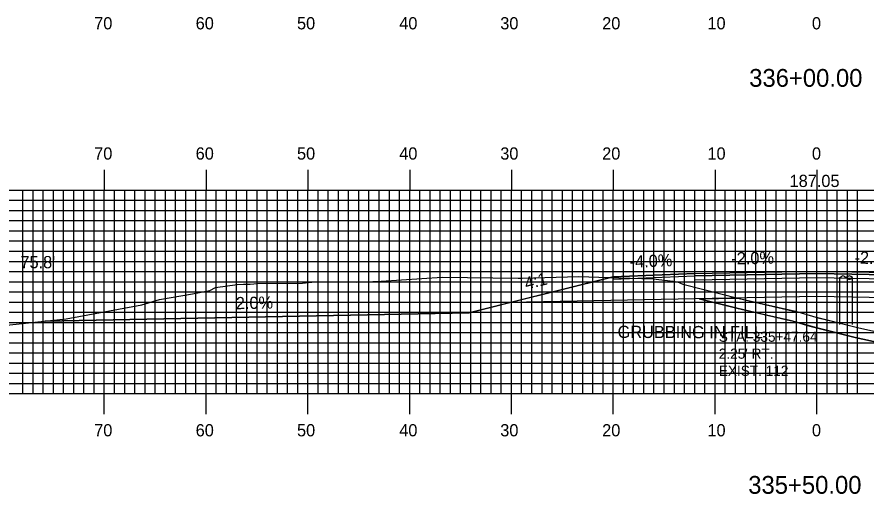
# Model space of a CAD drawing. Extents: x 1823573 to 1823916, y 442591 to 442811.
# Drawn here: x 1823659.7 to 1823743.1, y 442638.8 to 442685.7 of the extents above; entities that cross this region are included whole.
import ezdxf

# ---------------------------------------------------------------- set-up
doc = ezdxf.new("R2010")
doc.units = 0
for name, color, linetype in [('ANNOTATION', 7, 'Continuous'), ('D_Roadway_Centerline', 7, 'Continuous'), ('D_Roadway_Centerline_Text', 7, 'Continuous'), ('D_Roadway_Edge_Shoulder', 7, 'Continuous'), ('D_Roadway_Edge_TW', 7, 'Continuous'), ('D_Roadway_Pavement', 7, 'Continuous'), ('D_Roadway_SlopeLines', 7, 'Continuous'), ('D_Roadway_SubGrade', 7, 'Continuous'), ('D_Text_Monospaced', 7, 'Continuous'), ('D_Text_Standard', 7, 'Continuous'), ('GRUBBING IN FILL', 7, 'Continuous'), ('H_V ANNOTATION', 7, 'Continuous'), ('MAJOR', 7, 'Continuous'), ('MINOR', 7, 'Continuous'), ('S_Roadway_Centerline', 7, 'Continuous'), ('S_Utilities_Pole_Power', 7, 'Continuous')]:
    doc.layers.add(name, color=color, linetype=linetype)

msp = doc.modelspace()

# ---------------------------------------------------------------- linework, layer by layer
at = {"layer": 'D_Roadway_Centerline'}
msp.add_lwpolyline([(1823662.489, 442655.78), (1823704.135, 442656.613), (1823708.135, 442657.613), (1823718.309, 442660.156), (1823726.309, 442660.476), (1823738.309, 442660.716), (1823750.309, 442660.476), (1823758.309, 442660.156), (1823768.483, 442657.613), (1823772.483, 442656.613), (1823781.16, 442654.443)], dxfattribs=at)
at = {"layer": 'D_Roadway_Edge_Shoulder'}
msp.add_lwpolyline([(1823726.309, 442660.476), (1823718.309, 442660.156), (1823718.309, 442659.906), (1823726.309, 442660.226)], close=True, dxfattribs=at)
at = {"layer": 'D_Roadway_Edge_TW'}
msp.add_lwpolyline([(1823726.309, 442660.226), (1823726.309, 442660.476), (1823738.309, 442660.716), (1823750.309, 442660.476), (1823750.309, 442660.226), (1823738.309, 442660.466)], close=True, dxfattribs=at)
at = {"layer": 'D_Roadway_Pavement'}
msp.add_lwpolyline([(1823726.309, 442659.81), (1823726.309, 442660.226), (1823738.309, 442660.466), (1823750.309, 442660.226), (1823750.309, 442659.81), (1823738.309, 442660.05)], close=True, dxfattribs=at)
at = {"layer": 'D_Roadway_SlopeLines'}
msp.add_lwpolyline([(1823718.309, 442660.156), (1823704.135, 442656.613), (1823662.489, 442655.78)], dxfattribs=at)
at = {"layer": 'D_Roadway_SubGrade'}
msp.add_lwpolyline([(1823726.309, 442657.976), (1823708.135, 442657.613), (1823718.309, 442660.156), (1823718.309, 442659.906), (1823726.309, 442660.226), (1823738.309, 442660.466), (1823750.309, 442660.226), (1823758.309, 442659.906), (1823758.309, 442660.156), (1823768.483, 442657.613), (1823750.309, 442657.976), (1823738.309, 442658.216)], close=True, dxfattribs=at)
at = {"layer": 'GRUBBING IN FILL'}
for points in [[(1823726.758, 442657.985), (1823730.549, 442658.061), (1823733.287, 442657.422), (1823736.201, 442656.765), (1823737.873, 442656.263), (1823738.309, 442656.153), (1823738.309, 442655.122), (1823735.834, 442655.812), (1823733.071, 442656.445), (1823730.45, 442657.055)], [(1823726.758, 442657.985), (1823730.549, 442658.061), (1823733.287, 442657.422), (1823736.201, 442656.765), (1823737.873, 442656.263), (1823738.309, 442656.153), (1823738.309, 442655.122), (1823735.834, 442655.812), (1823733.071, 442656.445), (1823730.45, 442657.055)], [(1823738.309, 442656.153), (1823740.088, 442655.707), (1823742.302, 442655.15), (1823744.793, 442654.614), (1823747.6, 442654.321), (1823750.408, 442654.027), (1823752.928, 442653.797), (1823758.157, 442653.904), (1823765.827, 442654.079), (1823768.483, 442654.139), (1823768.483, 442653.139), (1823763.33, 442653.022), (1823758.178, 442652.905), (1823755.535, 442652.85), (1823752.893, 442652.796), (1823747.473, 442653.329), (1823744.635, 442653.625), (1823742.075, 442654.176), (1823738.309, 442655.122)], [(1823738.309, 442656.153), (1823740.088, 442655.707), (1823742.302, 442655.15), (1823744.793, 442654.614), (1823747.6, 442654.321), (1823750.408, 442654.027), (1823752.928, 442653.797), (1823758.157, 442653.904), (1823765.827, 442654.079), (1823768.483, 442654.139), (1823768.483, 442653.139), (1823763.33, 442653.022), (1823758.178, 442652.905), (1823755.535, 442652.85), (1823752.893, 442652.796), (1823747.473, 442653.329), (1823744.635, 442653.625), (1823742.075, 442654.176), (1823738.309, 442655.122)]]:
    msp.add_lwpolyline(points, close=True, dxfattribs=at)
msp.add_lwpolyline([(1823726.758, 442657.985), (1823730.45, 442657.055), (1823735.693, 442655.836), (1823735.975, 442655.789), (1823737.608, 442655.298), (1823742.075, 442654.176), (1823744.635, 442653.625), (1823750.31, 442653.032), (1823752.893, 442652.796), (1823758.178, 442652.905), (1823768.483, 442653.139)], dxfattribs=at)
msp.add_lwpolyline([(1823726.758, 442657.985), (1823730.45, 442657.055), (1823735.693, 442655.836), (1823735.975, 442655.789), (1823737.608, 442655.298), (1823742.075, 442654.176), (1823744.635, 442653.625), (1823750.31, 442653.032), (1823752.893, 442652.796), (1823758.178, 442652.905), (1823768.483, 442653.139)], dxfattribs=at)
at = {"layer": 'MAJOR'}
for p, q in [((1823668.309, 442670.669), (1823668.309, 442668.665)), ((1823678.309, 442670.669), (1823678.309, 442668.665)), ((1823688.309, 442670.669), (1823688.309, 442668.665)), ((1823698.309, 442670.669), (1823698.309, 442668.665)), ((1823708.309, 442670.669), (1823708.309, 442668.665)), ((1823718.309, 442670.669), (1823718.309, 442668.665)), ((1823728.309, 442670.669), (1823728.309, 442668.665)), ((1823738.309, 442670.669), (1823738.309, 442668.665)), ((1823598.309, 442668.665), (1823878.309, 442668.665)), ((1823598.309, 442668.665), (1823878.309, 442668.665)), ((1823668.309, 442648.665), (1823668.309, 442668.665)), ((1823678.309, 442648.665), (1823678.309, 442668.665)), ((1823688.309, 442648.665), (1823688.309, 442668.665)), ((1823698.309, 442648.665), (1823698.309, 442668.665)), ((1823708.309, 442648.665), (1823708.309, 442668.665)), ((1823718.309, 442648.665), (1823718.309, 442668.665)), ((1823728.309, 442648.665), (1823728.309, 442668.665)), ((1823738.309, 442648.665), (1823738.309, 442668.665)), ((1823598.309, 442663.665), (1823878.309, 442663.665)), ((1823598.309, 442658.665), (1823878.309, 442658.665)), ((1823598.309, 442653.665), (1823878.309, 442653.665)), ((1823598.309, 442648.665), (1823878.309, 442648.665)), ((1823598.309, 442648.665), (1823878.309, 442648.665)), ((1823668.309, 442646.661), (1823668.309, 442648.665)), ((1823678.309, 442646.661), (1823678.309, 442648.665)), ((1823688.309, 442646.661), (1823688.309, 442648.665)), ((1823698.309, 442646.661), (1823698.309, 442648.665)), ((1823708.309, 442646.661), (1823708.309, 442648.665)), ((1823718.309, 442646.661), (1823718.309, 442648.665)), ((1823728.309, 442646.661), (1823728.309, 442648.665)), ((1823738.309, 442646.661), (1823738.309, 442648.665))]:
    msp.add_line(p, q, dxfattribs=at)
at = {"layer": 'MINOR'}
for p, q in [((1823660.309, 442648.665), (1823660.309, 442668.665)), ((1823661.309, 442648.665), (1823661.309, 442668.665)), ((1823662.309, 442648.665), (1823662.309, 442668.665)), ((1823663.309, 442648.665), (1823663.309, 442668.665)), ((1823664.309, 442648.665), (1823664.309, 442668.665)), ((1823665.309, 442648.665), (1823665.309, 442668.665)), ((1823666.309, 442648.665), (1823666.309, 442668.665)), ((1823667.309, 442648.665), (1823667.309, 442668.665)), ((1823669.309, 442648.665), (1823669.309, 442668.665)), ((1823670.309, 442648.665), (1823670.309, 442668.665)), ((1823671.309, 442648.665), (1823671.309, 442668.665)), ((1823672.309, 442648.665), (1823672.309, 442668.665)), ((1823673.309, 442648.665), (1823673.309, 442668.665)), ((1823674.309, 442648.665), (1823674.309, 442668.665)), ((1823675.309, 442648.665), (1823675.309, 442668.665)), ((1823676.309, 442648.665), (1823676.309, 442668.665)), ((1823677.309, 442648.665), (1823677.309, 442668.665)), ((1823679.309, 442648.665), (1823679.309, 442668.665)), ((1823680.309, 442648.665), (1823680.309, 442668.665)), ((1823681.309, 442648.665), (1823681.309, 442668.665)), ((1823682.309, 442648.665), (1823682.309, 442668.665)), ((1823683.309, 442648.665), (1823683.309, 442668.665)), ((1823684.309, 442648.665), (1823684.309, 442668.665)), ((1823685.309, 442648.665), (1823685.309, 442668.665)), ((1823686.309, 442648.665), (1823686.309, 442668.665)), ((1823687.309, 442648.665), (1823687.309, 442668.665)), ((1823689.309, 442648.665), (1823689.309, 442668.665)), ((1823690.309, 442648.665), (1823690.309, 442668.665)), ((1823691.309, 442648.665), (1823691.309, 442668.665)), ((1823692.309, 442648.665), (1823692.309, 442668.665)), ((1823693.309, 442648.665), (1823693.309, 442668.665)), ((1823694.309, 442648.665), (1823694.309, 442668.665)), ((1823695.309, 442648.665), (1823695.309, 442668.665)), ((1823696.309, 442648.665), (1823696.309, 442668.665)), ((1823697.309, 442648.665), (1823697.309, 442668.665)), ((1823699.309, 442648.665), (1823699.309, 442668.665)), ((1823700.309, 442648.665), (1823700.309, 442668.665)), ((1823701.309, 442648.665), (1823701.309, 442668.665)), ((1823702.309, 442648.665), (1823702.309, 442668.665)), ((1823703.309, 442648.665), (1823703.309, 442668.665)), ((1823704.309, 442648.665), (1823704.309, 442668.665)), ((1823705.309, 442648.665), (1823705.309, 442668.665)), ((1823706.309, 442648.665), (1823706.309, 442668.665)), ((1823707.309, 442648.665), (1823707.309, 442668.665)), ((1823709.309, 442648.665), (1823709.309, 442668.665)), ((1823710.309, 442648.665), (1823710.309, 442668.665)), ((1823711.309, 442648.665), (1823711.309, 442668.665)), ((1823712.309, 442648.665), (1823712.309, 442668.665)), ((1823713.309, 442648.665), (1823713.309, 442668.665)), ((1823714.309, 442648.665), (1823714.309, 442668.665)), ((1823715.309, 442648.665), (1823715.309, 442668.665)), ((1823716.309, 442648.665), (1823716.309, 442668.665)), ((1823717.309, 442648.665), (1823717.309, 442668.665)), ((1823719.309, 442648.665), (1823719.309, 442668.665)), ((1823720.309, 442648.665), (1823720.309, 442668.665)), ((1823721.309, 442648.665), (1823721.309, 442668.665)), ((1823722.309, 442648.665), (1823722.309, 442668.665)), ((1823723.309, 442648.665), (1823723.309, 442668.665)), ((1823724.309, 442648.665), (1823724.309, 442668.665)), ((1823725.309, 442648.665), (1823725.309, 442668.665)), ((1823726.309, 442648.665), (1823726.309, 442668.665)), ((1823727.309, 442648.665), (1823727.309, 442668.665)), ((1823729.309, 442648.665), (1823729.309, 442668.665)), ((1823730.309, 442648.665), (1823730.309, 442668.665)), ((1823731.309, 442648.665), (1823731.309, 442668.665)), ((1823732.309, 442648.665), (1823732.309, 442668.665)), ((1823733.309, 442648.665), (1823733.309, 442668.665)), ((1823734.309, 442648.665), (1823734.309, 442668.665)), ((1823735.309, 442648.665), (1823735.309, 442668.665)), ((1823736.309, 442648.665), (1823736.309, 442668.665)), ((1823737.309, 442648.665), (1823737.309, 442668.665)), ((1823739.309, 442648.665), (1823739.309, 442668.665)), ((1823740.309, 442648.665), (1823740.309, 442668.665)), ((1823741.309, 442648.665), (1823741.309, 442668.665)), ((1823742.309, 442648.665), (1823742.309, 442668.665)), ((1823598.309, 442667.665), (1823878.309, 442667.665)), ((1823598.309, 442666.665), (1823878.309, 442666.665)), ((1823598.309, 442665.665), (1823878.309, 442665.665)), ((1823598.309, 442664.665), (1823878.309, 442664.665)), ((1823598.309, 442662.665), (1823878.309, 442662.665)), ((1823598.309, 442661.665), (1823878.309, 442661.665)), ((1823598.309, 442660.665), (1823878.309, 442660.665)), ((1823598.309, 442659.665), (1823878.309, 442659.665)), ((1823598.309, 442657.665), (1823878.309, 442657.665)), ((1823598.309, 442656.665), (1823878.309, 442656.665)), ((1823598.309, 442655.665), (1823878.309, 442655.665)), ((1823598.309, 442654.665), (1823878.309, 442654.665)), ((1823598.309, 442652.665), (1823878.309, 442652.665)), ((1823598.309, 442651.665), (1823878.309, 442651.665)), ((1823598.309, 442650.665), (1823878.309, 442650.665)), ((1823598.309, 442649.665), (1823878.309, 442649.665))]:
    msp.add_line(p, q, dxfattribs=at)
at = {"layer": 'S_Roadway_Centerline'}
msp.add_lwpolyline([(1823658.39, 442655.346), (1823664.567, 442656), (1823667.929, 442656.646), (1823671.985, 442657.384), (1823673.72, 442657.904), (1823676.973, 442658.467), (1823678.661, 442658.791), (1823679.244, 442659.11), (1823681.364, 442659.375), (1823681.975, 442659.428), (1823682.641, 442659.432), (1823683.35, 442659.478), (1823687.777, 442659.514), (1823689.001, 442659.643), (1823693.077, 442659.634), (1823695.518, 442659.729), (1823701.507, 442660.118), (1823708.953, 442660.007), (1823709.342, 442660.009), (1823714.909, 442660.19), (1823718.839, 442660.058), (1823722.223, 442659.953), (1823724.192, 442659.708), (1823724.602, 442659.654), (1823725.133, 442659.426), (1823730.686, 442658.027), (1823735.888, 442656.817), (1823736.201, 442656.765), (1823737.873, 442656.263), (1823742.302, 442655.15), (1823744.793, 442654.614)], dxfattribs=at)
at = {"layer": 'S_Utilities_Pole_Power'}
for p, q in [((1823740.562, 442655.449), (1823740.559, 442660.068)), ((1823740.562, 442660.068), (1823740.718, 442660.178)), ((1823741.031, 442660.178), (1823741.187, 442660.068)), ((1823741.344, 442660.178), (1823741.187, 442660.068)), ((1823741.187, 442660.068), (1823741.344, 442659.957)), ((1823741.812, 442660.068), (1823741.656, 442660.178)), ((1823741.656, 442659.957), (1823741.812, 442660.068)), ((1823741.812, 442655.449), (1823741.809, 442660.068))]:
    msp.add_line(p, q, dxfattribs=at)
for centre, start, end in [((1823740.874, 442659.958), 90, 125.26439), ((1823740.874, 442659.958), 54.73561, 90), ((1823741.499, 442659.958), 90, 125.26439), ((1823741.499, 442660.178), 234.73561, 270), ((1823741.499, 442659.958), 54.73561, 90), ((1823741.499, 442660.178), 270, 305.26439)]:
    msp.add_arc(centre, 0.271, start, end, dxfattribs=at)

# ---------------------------------------------------------------- texts
at = {"layer": 'ANNOTATION'}
for s, rotation, p in [('-4.0%', 2.29061, (1823719.94, 442661.023)), ('-2.0%', 1.14576, (1823729.915, 442661.349)), ('-2.0%', 358.85424, (1823741.995, 442661.443)), ('4:1', 14.03624, (1823709.757, 442658.88)), ('2.0%', 1.14576, (1823681.239, 442656.955))]:
    msp.add_text(s, height=1.2, rotation=rotation, dxfattribs=at).set_placement(p)
at = {"layer": 'D_Roadway_Centerline'}
for s, p in [('C', (1823738.303, 442660.716)), ('L', (1823738.309, 442660.709))]:
    msp.add_text(s, height=0.0146, dxfattribs=at).set_placement(p)
at = {"layer": 'D_Roadway_Centerline_Text'}
msp.add_text('187.05', height=1.2, dxfattribs=at).set_placement((1823735.628, 442668.971))
at = {"layer": 'D_Text_Monospaced'}
for s, height, p in [('STA. 335+47.64', 0.99996, (1823728.675, 442653.759)), ("2.25' RT.", 1, (1823728.675, 442652.091)), ('EXIST. 112', 1, (1823728.675, 442650.411))]:
    msp.add_text(s, height=height, dxfattribs=at).set_placement(p)
at = {"layer": 'D_Text_Standard'}
msp.add_text("75.8'", height=1.2, dxfattribs=at).set_placement((1823660.065, 442660.986))
at = {"layer": 'GRUBBING IN FILL'}
msp.add_text('GRUBBING IN FILL', height=1.2, rotation=359.80532, dxfattribs=at).set_placement((1823718.732, 442654.139))
at = {"layer": 'H_V ANNOTATION'}
for s, height, p in [('70', 1.2, (1823667.313, 442684.465)), ('60', 1.2, (1823677.281, 442684.465)), ('50', 1.2, (1823687.238, 442684.465)), ('40', 1.2, (1823697.281, 442684.465)), ('30', 1.2, (1823707.206, 442684.465)), ('20', 1.2, (1823717.217, 442684.465)), ('10', 1.2, (1823727.559, 442684.465)), ('0', 1.2, (1823737.827, 442684.465)), ('336+00.00', 1.75, (1823731.661, 442678.821)), ('70', 1.2, (1823667.313, 442671.665)), ('60', 1.2, (1823677.281, 442671.665)), ('50', 1.2, (1823687.238, 442671.665)), ('40', 1.2, (1823697.281, 442671.665)), ('30', 1.2, (1823707.206, 442671.665)), ('20', 1.2, (1823717.217, 442671.665)), ('10', 1.2, (1823727.559, 442671.665)), ('0', 1.2, (1823737.827, 442671.665)), ('70', 1.2, (1823667.313, 442644.465)), ('60', 1.2, (1823677.281, 442644.465)), ('50', 1.2, (1823687.238, 442644.465)), ('40', 1.2, (1823697.281, 442644.465)), ('30', 1.2, (1823707.206, 442644.465)), ('20', 1.2, (1823717.217, 442644.465)), ('10', 1.2, (1823727.559, 442644.465)), ('0', 1.2, (1823737.827, 442644.465)), ('335+50.00', 1.75, (1823731.567, 442638.821))]:
    msp.add_text(s, height=height, dxfattribs=at).set_placement(p)
at = {"layer": 'S_Roadway_Centerline'}
for s, p in [('L', (1823701.498, 442660.111)), ('C', (1823701.502, 442660.118))]:
    msp.add_text(s, height=0.0146, dxfattribs=at).set_placement(p)

doc.saveas('drawing.dxf')
